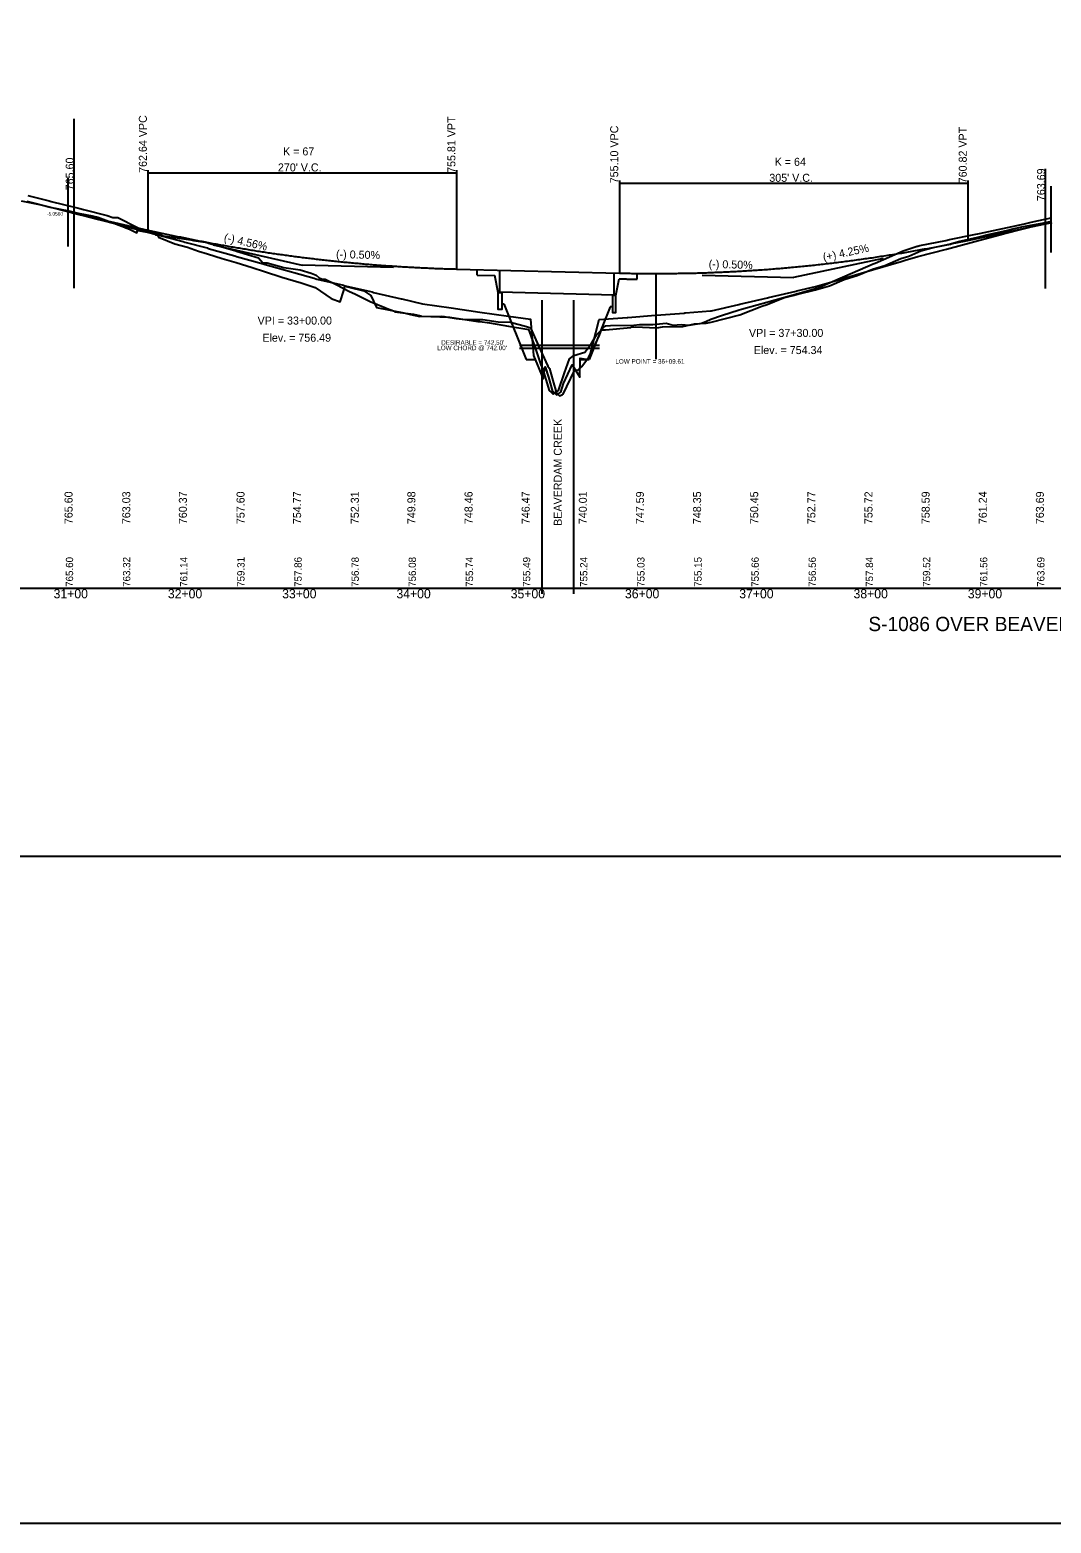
# Model space of a CAD drawing. Extents: x 1935020 to 1938620, y 1201670 to 1203870.
# Drawn here: x 1936846 to 1937739, y 1201670 to 1202977 of the extents above; entities that cross this region are included whole.
import ezdxf

# ---------------------------------------------------------------- set-up
doc = ezdxf.new("R2010")
doc.units = 0
for name, color, linetype in [('BR_CONCRETE', 7, 'Continuous'), ('BR_EXIST_GROUND_LT', 7, 'Continuous'), ('BR_EXIST_GROUND_RT', 7, 'Continuous'), ('BR_USER NOTES', 7, 'Continuous'), ('RD_DDB_GradeTX', 7, 'Continuous'), ('RD_DDB_Profile_EX', 7, 'Continuous'), ('RD_DDB_Profile_Lbl', 7, 'Continuous'), ('RD_DDB_Profile_PR', 7, 'Continuous'), ('RD_DDB_StaTX', 7, 'Continuous'), ('RD_DDB_StripGrade', 7, 'Continuous'), ('RD_DDB_VCLbl', 7, 'Continuous'), ('RD_GPK_Profile_Cell', 7, 'Continuous'), ('RD_SHT_IplotShp', 7, 'Continuous'), ('RD_SHT_ShtClip', 7, 'Continuous'), ('RD_SHT_TX', 7, 'Continuous')]:
    doc.layers.add(name, color=color, linetype=linetype)

msp = doc.modelspace()

# ---------------------------------------------------------------- linework, layer by layer
at = {"layer": 'BR_CONCRETE'}
for p, q in [((1937236.9, 1202762.2), (1937236.9, 1202767.2)), ((1937256.9, 1202747.6), (1937256.9, 1202766.4)), ((1937356.9, 1202745.1), (1937356.9, 1202764.2)), ((1937376.9, 1202758.8), (1937376.9, 1202763.8)), ((1937236.9, 1202762.2), (1937252.4, 1202761.8)), ((1937255.4, 1202747.1), (1937252.4, 1202761.8)), ((1937358.4, 1202744.5), (1937361.3, 1202759)), ((1937256.9, 1202747.6), (1937356.9, 1202745.1)), ((1937256.9, 1202747.6), (1937256.9, 1202747.1)), ((1937356.9, 1202745.1), (1937356.9, 1202744.5)), ((1937258.4, 1202737.1), (1937260.4, 1202737.1)), ((1937260.4, 1202737.1), (1937279.8, 1202688.5)), ((1937353.4, 1202734.6), (1937334.9, 1202688.5)), ((1937355.4, 1202734.6), (1937353.4, 1202734.6)), ((1937279.8, 1202688.5), (1937287.6, 1202688.5)), ((1937327.1, 1202688.5), (1937334.9, 1202688.5))]:
    msp.add_line(p, q, dxfattribs=at)
for points in [[(1937255.4, 1202747.1), (1937258.4, 1202747.1), (1937258.4, 1202732.1), (1937255.4, 1202732.1)], [(1937358.4, 1202744.5), (1937355.4, 1202744.5), (1937355.4, 1202729.5), (1937358.4, 1202729.5)]]:
    msp.add_lwpolyline(points, close=True, dxfattribs=at)
msp.add_open_spline([(1937361.3, 1202759), (1937361.9, 1202759), (1937362.6, 1202758.9), (1937364, 1202758.9), (1937364.8, 1202758.9), (1937365.6, 1202758.9), (1937365.7, 1202758.9), (1937365.7, 1202758.9), (1937365.8, 1202758.9), (1937365.8, 1202758.9), (1937365.9, 1202758.9), (1937366.3, 1202758.9), (1937367, 1202758.9), (1937369.1, 1202758.8), (1937371.1, 1202758.8), (1937374.1, 1202758.8), (1937375.5, 1202758.8), (1937376.9, 1202758.8)], degree=3, dxfattribs=at)
at = {"layer": 'BR_EXIST_GROUND_LT'}
msp.add_line((1937293.7, 1202483.5), (1937293.7, 1202740.4), dxfattribs=at)
msp.add_lwpolyline([(1936843.7, 1202832), (1936862.4, 1202827.2), (1936864.2, 1202826.8), (1936885.7, 1202821.4), (1936889.2, 1202820.5), (1936892.4, 1202819.7), (1936913.3, 1202814.4), (1936918.2, 1202812.6), (1936922.6, 1202812.6), (1936939.6, 1202803.8), (1936945, 1202800.9), (1936946.4, 1202800.8), (1936949.6, 1202800.4), (1936958.8, 1202798.3), (1936962.2, 1202796.7), (1936986.4, 1202793), (1936988.7, 1202792.6), (1936998.9, 1202791.1), (1937001.2, 1202790.5), (1937001.8, 1202790.3), (1937012.7, 1202787.3), (1937025.9, 1202783.4), (1937026.4, 1202783.2), (1937045.7, 1202777.4), (1937049.4, 1202773), (1937053.1, 1202773), (1937067.7, 1202768.9), (1937082, 1202766.8), (1937091.8, 1202764.1), (1937096, 1202762.2), (1937098.6, 1202759.8), (1937100.8, 1202759), (1937103.9, 1202758.7), (1937113.6, 1202754.1), (1937125.1, 1202747.9), (1937129.9, 1202745.8), (1937143.2, 1202739.1), (1937156.3, 1202733.9), (1937158.3, 1202733), (1937164.6, 1202730.6), (1937165, 1202730.2), (1937181.3, 1202728.2), (1937187.6, 1202726.6), (1937188.2, 1202726.5), (1937212.5, 1202725.5), (1937212.9, 1202725.5), (1937237.6, 1202721.8), (1937239.2, 1202721.6), (1937247.8, 1202720.4), (1937264.4, 1202717.7), (1937280.5, 1202715), (1937281.9, 1202714.7), (1937282.7, 1202712.4), (1937287.9, 1202697.7), (1937292.6, 1202683.8), (1937293.3, 1202682.9), (1937294, 1202680.6), (1937299.9, 1202661.4), (1937301.7, 1202659.8), (1937303.6, 1202658.2), (1937306.1, 1202660), (1937308.1, 1202661.4), (1937313.3, 1202676.9), (1937317.9, 1202688.9), (1937321.6, 1202691.8), (1937331.3, 1202694.9), (1937336.3, 1202701.7), (1937341.4, 1202710), (1937348.6, 1202717.7), (1937349.2, 1202717.9), (1937353.7, 1202718.2), (1937374.1, 1202718.6), (1937378.9, 1202719), (1937390.8, 1202719.2), (1937402.3, 1202720.3), (1937408.5, 1202718.6), (1937415.5, 1202719), (1937422.6, 1202718.4), (1937433.3, 1202720.1), (1937437.1, 1202721.7), (1937441.3, 1202723.8), (1937450.8, 1202726.8), (1937466.3, 1202731.8), (1937468.4, 1202732.4), (1937473.4, 1202734), (1937490.3, 1202738.5), (1937492.4, 1202739.3), (1937517.5, 1202746.2), (1937535.1, 1202751), (1937558.7, 1202761.3), (1937583.4, 1202772.1), (1937585.3, 1202772.8), (1937609.7, 1202783.6), (1937622, 1202787.6), (1937622.5, 1202787.7), (1937624.3, 1202788.1), (1937647, 1202792.6), (1937650.4, 1202793.4), (1937672, 1202797.7), (1937676.5, 1202798.8), (1937697, 1202803), (1937701, 1202804), (1937715.8, 1202807), (1937721.7, 1202808.6), (1937739.2, 1202812.5)], dxfattribs=at)
at = {"layer": 'BR_EXIST_GROUND_RT'}
msp.add_line((1937321.5, 1202483.5), (1937321.5, 1202740.4), dxfattribs=at)
msp.add_lwpolyline([(1936838, 1202827.2), (1936853.9, 1202824), (1936862.9, 1202821.8), (1936879.7, 1202818.5), (1936887.8, 1202816.6), (1936900, 1202814.2), (1936904.9, 1202813), (1936928.2, 1202804.1), (1936929.5, 1202803.7), (1936929.8, 1202803.6), (1936933.2, 1202802.2), (1936939.1, 1202799.3), (1936939.8, 1202801.2), (1936941.9, 1202801), (1936954.9, 1202798.7), (1936955.6, 1202797.5), (1936957.2, 1202797.3), (1936958.1, 1202795.6), (1936972.5, 1202789.6), (1936983.4, 1202786.8), (1936993, 1202783.1), (1937001.1, 1202781), (1937013.9, 1202776.9), (1937026.1, 1202773.2), (1937040, 1202768.8), (1937051, 1202765.4), (1937066, 1202760.6), (1937075.9, 1202757.5), (1937082.8, 1202755.4), (1937095.1, 1202751.5), (1937109.3, 1202741.7), (1937117.1, 1202739), (1937120.2, 1202748.8), (1937120.4, 1202748.9), (1937121.2, 1202752.6), (1937124.8, 1202751.6), (1937137.7, 1202748.4), (1937143.1, 1202745), (1937143.9, 1202744.3), (1937149, 1202733.8), (1937172.8, 1202729.3), (1937178.7, 1202727.8), (1937186.7, 1202726.2), (1937205.9, 1202726.4), (1937208.1, 1202726), (1937211.3, 1202725.6), (1937218.7, 1202724.4), (1937226.4, 1202723.3), (1937242, 1202723.3), (1937255.2, 1202721.4), (1937266.2, 1202721), (1937280.2, 1202717.3), (1937283.7, 1202716.2), (1937290.6, 1202700.5), (1937298.8, 1202682.6), (1937300.4, 1202680.6), (1937303.1, 1202670.2), (1937306.3, 1202659), (1937309, 1202656.6), (1937311.2, 1202657.6), (1937312.1, 1202658), (1937322.2, 1202678.8), (1937325.2, 1202679.3), (1937328.6, 1202682.2), (1937334.5, 1202690.2), (1937343.4, 1202708.4), (1937345.9, 1202714.3), (1937349.4, 1202714.5), (1937371.3, 1202716.5), (1937371.8, 1202716.6), (1937375.2, 1202716.9), (1937394.2, 1202716.2), (1937399, 1202717.1), (1937416.8, 1202717.3), (1937427, 1202719.6), (1937437.4, 1202720.1), (1937441.7, 1202721.2), (1937466.8, 1202727.4), (1937486.2, 1202735), (1937490.7, 1202736.6), (1937505, 1202742.5), (1937513.2, 1202744.5), (1937517.6, 1202745.6), (1937533, 1202749.3), (1937545.4, 1202753), (1937558, 1202758.3), (1937569.6, 1202761.8), (1937582.9, 1202767.4), (1937593.8, 1202770.8), (1937607.8, 1202776.8), (1937614.7, 1202778.9), (1937622.5, 1202782.3), (1937625.2, 1202783.4), (1937634.7, 1202786), (1937650.1, 1202789.4), (1937659.4, 1202791.9), (1937675.1, 1202795.4), (1937684, 1202797.8), (1937700.1, 1202801.3), (1937705.6, 1202802.8), (1937714.9, 1202804.9), (1937731.4, 1202807.8), (1937739.9, 1202809.5)], dxfattribs=at)
at = {"layer": 'BR_USER NOTES'}
for p, q in [((1936883.9, 1202899.1), (1936883.9, 1202750.8)), ((1937733.9, 1202855.2), (1937733.9, 1202750.5)), ((1936878.9, 1202847.1), (1936878.9, 1202787.3)), ((1937738.9, 1202840.2), (1937738.9, 1202782.2)), ((1936878.9, 1202817.8), (1936883.9, 1202816.5)), ((1937733.9, 1202807), (1937738.9, 1202808)), ((1937393.5, 1202688.8), (1937393.5, 1202763.6)), ((1937273.9, 1202701), (1937343.9, 1202701)), ((1937273.9, 1202698.5), (1937343.9, 1202698.5))]:
    msp.add_line(p, q, dxfattribs=at)
at = {"layer": 'RD_DDB_GradeTX'}
for p, q in [((1937005.9, 1202788.8), (1937083.9, 1202771)), ((1937592.1, 1202776.9), (1937513.9, 1202760.2)), ((1937163.8, 1202769), (1937083.9, 1202771)), ((1937433.9, 1202762.2), (1937513.9, 1202760.2))]:
    msp.add_line(p, q, dxfattribs=at)
at = {"layer": 'RD_DDB_Profile_EX'}
msp.add_lwpolyline([(1936842.8, 1202826.9), (1936864.8, 1202821.4), (1936867.5, 1202820.7), (1936889.8, 1202815.1), (1936891.4, 1202814.6), (1936905.9, 1202811), (1936908.2, 1202810.4), (1936930.9, 1202804.4), (1936932.2, 1202804.1), (1936955.2, 1202798.1), (1936956.3, 1202797.8), (1936979.6, 1202791.6), (1936981.2, 1202791.1), (1937000.6, 1202786), (1937001.5, 1202785.7), (1937024.9, 1202779.1), (1937026.5, 1202778.7), (1937049.6, 1202772.1), (1937051.4, 1202771.6), (1937074.4, 1202765.1), (1937076.4, 1202764.5), (1937094.2, 1202759.5), (1937095.8, 1202759), (1937096.7, 1202758.8), (1937119.9, 1202753.4), (1937121.4, 1202753), (1937145.1, 1202747.5), (1937146.2, 1202747.2), (1937170.4, 1202741.6), (1937170.9, 1202741.5), (1937189.2, 1202737.2), (1937214.2, 1202733.6), (1937239.3, 1202730), (1937264.3, 1202726.5), (1937283.6, 1202723.7), (1937286.2, 1202691.9), (1937294.6, 1202671.4), (1937296.6, 1202682), (1937299.3, 1202673), (1937302.9, 1202660.4), (1937304.2, 1202659.6), (1937306.3, 1202657.5), (1937308.4, 1202658.7), (1937310.1, 1202659.9), (1937312.6, 1202667.4), (1937320.2, 1202683.7), (1937326.9, 1202673), (1937327.1, 1202689.6), (1937334.4, 1202688.5), (1937334.7, 1202689), (1937335.2, 1202690.4), (1937343.7, 1202723.4), (1937368.2, 1202725.3), (1937368.7, 1202725.3), (1937393.1, 1202727.2), (1937393.7, 1202727.2), (1937418, 1202729.1), (1937418.7, 1202729.2), (1937419.4, 1202729.2), (1937441, 1202730.9), (1937441.9, 1202731.1), (1937466, 1202736.6), (1937466.9, 1202736.8), (1937491, 1202742.4), (1937491.8, 1202742.6), (1937516, 1202748.2), (1937516.6, 1202748.4), (1937533.1, 1202752.2), (1937557.5, 1202759.4), (1937558.1, 1202759.6), (1937583, 1202766.9), (1937608, 1202774.2), (1937611.5, 1202775.3), (1937622.6, 1202778.5), (1937647.6, 1202785.1), (1937672.5, 1202791.8), (1937697.5, 1202798.4), (1937714.8, 1202802.9), (1937723, 1202804.7), (1937740, 1202808.3)], dxfattribs=at)
at = {"layer": 'RD_DDB_Profile_PR'}
for p, q in [((1936883.9, 1202816.5), (1936948.9, 1202801.7)), ((1937666.4, 1202792.6), (1937733.9, 1202807)), ((1937218.9, 1202767.6), (1937361.4, 1202764.1))]:
    msp.add_line(p, q, dxfattribs=at)
for points in [[(1936948.9, 1202801.7), (1936954.3, 1202800.5), (1936959.7, 1202799.3), (1936965.1, 1202798.1), (1936970.5, 1202797), (1936975.9, 1202795.9), (1936981.3, 1202794.8), (1936986.7, 1202793.7), (1936992.1, 1202792.6), (1936997.5, 1202791.6), (1937002.9, 1202790.5), (1937008.3, 1202789.5), (1937013.7, 1202788.6), (1937019.1, 1202787.6), (1937024.5, 1202786.7), (1937029.9, 1202785.8), (1937035.3, 1202784.9), (1937040.7, 1202784), (1937046.1, 1202783.1), (1937051.5, 1202782.3), (1937056.9, 1202781.5), (1937062.3, 1202780.7), (1937067.7, 1202780), (1937073.1, 1202779.2), (1937078.5, 1202778.5), (1937083.9, 1202777.8), (1937089.3, 1202777.2), (1937094.7, 1202776.5), (1937100.1, 1202775.9), (1937105.5, 1202775.3), (1937110.9, 1202774.7), (1937116.3, 1202774.1), (1937121.7, 1202773.6), (1937127.1, 1202773.1), (1937132.5, 1202772.6), (1937137.9, 1202772.1), (1937143.3, 1202771.6), (1937148.7, 1202771.2), (1937154.1, 1202770.8), (1937159.5, 1202770.4), (1937164.9, 1202770.1), (1937170.3, 1202769.7), (1937175.7, 1202769.4), (1937181.1, 1202769.1), (1937186.5, 1202768.8), (1937191.9, 1202768.6), (1937197.3, 1202768.3), (1937202.7, 1202768.1), (1937208.1, 1202767.9), (1937213.5, 1202767.8), (1937218.9, 1202767.6)], [(1937361.4, 1202764.1), (1937367.5, 1202763.9), (1937373.6, 1202763.8), (1937379.7, 1202763.7), (1937385.8, 1202763.7), (1937391.9, 1202763.6), (1937398, 1202763.7), (1937404.1, 1202763.7), (1937410.2, 1202763.8), (1937416.3, 1202763.9), (1937422.4, 1202764), (1937428.5, 1202764.1), (1937434.6, 1202764.3), (1937440.7, 1202764.5), (1937446.8, 1202764.8), (1937452.9, 1202765), (1937459, 1202765.3), (1937465.1, 1202765.6), (1937471.2, 1202766), (1937477.3, 1202766.4), (1937483.4, 1202766.8), (1937489.5, 1202767.2), (1937495.6, 1202767.7), (1937501.7, 1202768.2), (1937507.8, 1202768.7), (1937513.9, 1202769.3), (1937520, 1202769.9), (1937526.1, 1202770.5), (1937532.2, 1202771.1), (1937538.3, 1202771.8), (1937544.4, 1202772.5), (1937550.5, 1202773.2), (1937556.6, 1202774), (1937562.7, 1202774.8), (1937568.8, 1202775.6), (1937574.9, 1202776.5), (1937581, 1202777.3), (1937587.1, 1202778.2), (1937593.2, 1202779.2), (1937599.3, 1202780.1), (1937605.4, 1202781.1), (1937611.5, 1202782.1), (1937617.6, 1202783.2), (1937623.7, 1202784.3), (1937629.8, 1202785.4), (1937635.9, 1202786.5), (1937642, 1202787.7), (1937648.1, 1202788.9), (1937654.2, 1202790.1), (1937660.3, 1202791.4), (1937666.4, 1202792.6)]]:
    msp.add_spline(points, degree=3, dxfattribs=at)
at = {"layer": 'RD_DDB_VCLbl'}
for p, q in [((1936948.9, 1202854.2), (1936948.9, 1202801.7)), ((1936948.9, 1202851.7), (1937218.9, 1202851.7)), ((1937218.9, 1202854.2), (1937218.9, 1202767.6)), ((1937361.4, 1202845.1), (1937361.4, 1202764.1)), ((1937361.4, 1202842.6), (1937666.4, 1202842.6)), ((1937666.4, 1202845.1), (1937666.4, 1202792.6))]:
    msp.add_line(p, q, dxfattribs=at)
at = {"layer": 'RD_GPK_Profile_Cell'}
msp.add_line((1935783.9, 1202488.5), (1937855.4, 1202488.5), dxfattribs=at)
at = {"layer": 'RD_SHT_IplotShp'}
msp.add_lwpolyline([(1935019.6, 1201670.4), (1938619.6, 1201670.4), (1938619.6, 1203870.4), (1935019.6, 1203870.4)], close=True, dxfattribs=at)
at = {"layer": 'RD_SHT_ShtClip'}
msp.add_lwpolyline([(1936235.5, 1203353.5), (1938035.5, 1203353.5), (1938035.5, 1202253.5), (1936235.5, 1202253.5)], close=True, dxfattribs=at)

# ---------------------------------------------------------------- texts
at = {"layer": 'BR_USER NOTES'}
for s, height, p in [('-5.0560', 3, (1936860.5, 1202814.4)), ("LOW CHORD @ 742.00'", 4, (1937202, 1202696.6)), ("DESIRABLE = 742.50'", 4, (1937205.5, 1202701.3)), ('LOW POINT = 36+09.61', 4, (1937357.9, 1202684.8))]:
    msp.add_text(s, height=height, dxfattribs=at).set_placement(p)
at = {"layer": 'RD_DDB_GradeTX'}
for s, rotation, p in [('(-) 4.56%', 347.167, (1937014.9, 1202792.1)), ('(-) 0.50%', 358.5679, (1937113.4, 1202777.2)), ('(+) 4.25%', 11.9938, (1937540.3, 1202774.4)), ('(-) 0.50%', 358.5679, (1937439.5, 1202768.6))]:
    msp.add_text(s, height=7, rotation=rotation, dxfattribs=at).set_placement(p)
at = {"layer": 'RD_DDB_Profile_Lbl'}
for s, p in [('765.60', (1936883.9, 1202836.5)), ('763.69', (1937733.9, 1202827)), ('BEAVERDAM CREEK', (1937311, 1202542.9))]:
    msp.add_text(s, height=7, rotation=90, dxfattribs=at).set_placement(p)
for s, p in [('VPI = 33+00.00', (1937044.8, 1202719)), ('Elev. = 756.49', (1937049, 1202704)), ('VPI = 37+30.00', (1937474.8, 1202708.2)), ('Elev. = 754.34', (1937479, 1202693.2))]:
    msp.add_text(s, height=7, dxfattribs=at).set_placement(p)
at = {"layer": 'RD_DDB_StaTX'}
for s, p in [('31+00', (1936866.3, 1202479.5)), ('32+00', (1936966.3, 1202479.5)), ('33+00', (1937066.3, 1202479.5)), ('34+00', (1937166.3, 1202479.5)), ('35+00', (1937266.3, 1202479.5)), ('36+00', (1937366.3, 1202479.5)), ('37+00', (1937466.3, 1202479.5)), ('38+00', (1937566.3, 1202479.5)), ('39+00', (1937666.3, 1202479.5))]:
    msp.add_text(s, height=8, dxfattribs=at).set_placement(p)
at = {"layer": 'RD_DDB_StripGrade'}
for s, height, p in [('762.64 VPC', 7, (1936947.9, 1202851.7)), ('755.81 VPT', 7, (1937217.9, 1202851.7)), ('755.10 VPC', 7, (1937360.4, 1202842.6)), ('760.82 VPT', 7, (1937665.4, 1202842.6)), ('765.60', 7, (1936882.9, 1202544.4)), ('763.03', 7, (1936933.4, 1202544.4)), ('760.37', 7, (1936982.9, 1202544.4)), ('757.60', 7, (1937033.4, 1202544.4)), ('754.77', 7, (1937082.9, 1202544.4)), ('752.31', 7, (1937133.4, 1202544.4)), ('749.98', 7, (1937182.9, 1202544.4)), ('748.46', 7, (1937232.9, 1202544.4)), ('746.47', 7, (1937282.9, 1202544.4)), ('740.01', 7, (1937332.9, 1202544.4)), ('747.59', 7, (1937382.9, 1202544.4)), ('748.35', 7, (1937432.9, 1202544.4)), ('750.45', 7, (1937482.9, 1202544.4)), ('752.77', 7, (1937532.9, 1202544.4)), ('755.72', 7, (1937582.9, 1202544.4)), ('758.59', 7, (1937632.9, 1202544.4)), ('761.24', 7, (1937682.9, 1202544.4)), ('763.69', 7, (1937732.9, 1202544.4)), ('765.60', 6.4, (1936883.4, 1202489.5)), ('763.32', 6.4, (1936933.4, 1202489.5)), ('761.14', 6.4, (1936983.4, 1202489.5)), ('759.31', 6.4, (1937033.4, 1202489.5)), ('757.86', 6.4, (1937083.4, 1202489.5)), ('756.78', 6.4, (1937133.4, 1202489.5)), ('756.08', 6.4, (1937183.4, 1202489.5)), ('755.74', 6.4, (1937233.4, 1202489.5)), ('755.49', 6.4, (1937283.4, 1202489.5)), ('755.24', 6.4, (1937333.4, 1202489.5)), ('755.03', 6.4, (1937383.4, 1202489.5)), ('755.15', 6.4, (1937433.4, 1202489.5)), ('755.66', 6.4, (1937483.4, 1202489.5)), ('756.56', 6.4, (1937533.4, 1202489.5)), ('757.84', 6.4, (1937583.4, 1202489.5)), ('759.52', 6.4, (1937633.4, 1202489.5)), ('761.56', 6.4, (1937683.4, 1202489.5)), ('763.69', 6.4, (1937733.4, 1202489.5))]:
    msp.add_text(s, height=height, rotation=90, dxfattribs=at).set_placement(p)
at = {"layer": 'RD_DDB_VCLbl'}
for s, p in [('K = 67', (1937067.1, 1202867)), ("270' V.C.", (1937062.6, 1202853)), ('K = 64', (1937497.3, 1202857.9)), ("305' V.C.", (1937492.6, 1202843.9))]:
    msp.add_text(s, height=7, dxfattribs=at).set_placement(p)
at = {"layer": 'RD_SHT_TX'}
msp.add_text('S-1086 OVER BEAVERDAM CREEK', height=12.499, rotation=360, dxfattribs=at).set_placement((1937579.3, 1202450.8))

doc.saveas('drawing.dxf')
